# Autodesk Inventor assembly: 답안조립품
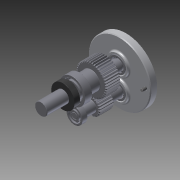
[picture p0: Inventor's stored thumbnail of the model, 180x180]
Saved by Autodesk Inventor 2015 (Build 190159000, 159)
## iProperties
Created: 2016-02
Part Number: 답안조립품
Document SubType Name: Assembly
Designer: Administrator
Author: Administrator
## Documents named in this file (10)
- C:\Users\Administrator\Desktop\460209V1010\답안조립품.iam
- C:\Users\Administrator\Desktop\460209V1010\본체.ipt
- C:\Users\Administrator\Desktop\460209V1010\커버.ipt
- C:\Users\Administrator\Desktop\460209V1010\오일실 17 32 8.ipt
- C:\Users\Administrator\Desktop\460209V1010\베어링 6003.ipt
- C:\Users\Administrator\Desktop\460209V1010\베어링 608.ipt
- C:\Users\Administrator\Desktop\460209V1010\서브축.ipt
- C:\Users\Administrator\Desktop\460209V1010\오일실 8 22 7.ipt
- C:\Users\Administrator\Desktop\460209V1010\볼트 M4 x 10.ipt
- C:\Users\Administrator\Desktop\460209V1010\메인축.ipt
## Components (2 placed, 1 different names)
1. ISO 4762 M4 x 10:1 — Insert:2
2. ISO 4762 M4 x 10:2 — Insert:1
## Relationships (2: Insert 2)
- Insert:1: ISO 4762 M4 x 10:2
- Insert:2: ISO 4762 M4 x 10:1
